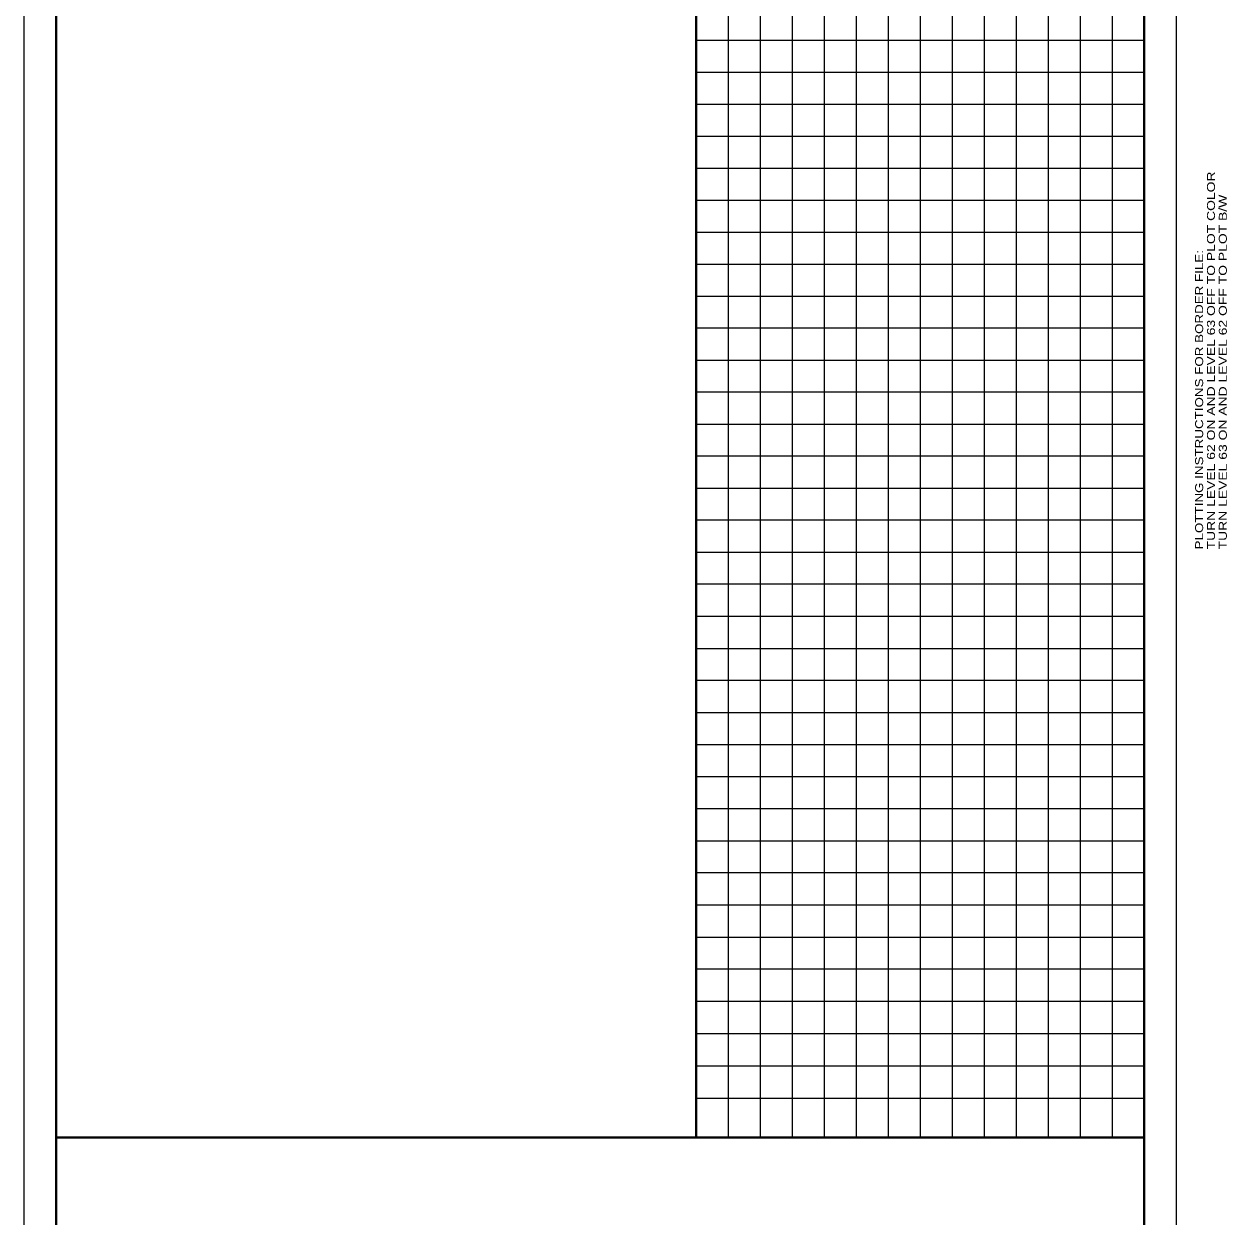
# Model space of a CAD drawing. Extents: x 2363323 to 2367082, y 6956018 to 6980837.
# Drawn here: x 2363323 to 2367082, y 6965978 to 6969706 of the extents above; entities that cross this region are included whole.
import ezdxf

# ---------------------------------------------------------------- set-up
doc = ezdxf.new("R2010")
doc.units = 0
doc.header["$LTSCALE"] = 4.1
doc.layers.add('1', color=7, linetype='Continuous')
for name, color, linetype, lineweight in [('61', 7, 'Continuous', 40), ('62', 7, 'Continuous', 13), ('63', 7, 'Continuous', 13)]:
    doc.layers.add(name, color=color, linetype=linetype, lineweight=lineweight)

msp = doc.modelspace()

# ---------------------------------------------------------------- linework, layer by layer
at = {"layer": '61'}
for p, q in [((2363423.186, 6980156.078), (2363423.186, 6957300.912)), ((2366823.34, 6966225.912), (2363423.186, 6966225.912))]:
    msp.add_line(p, q, dxfattribs=at)
at = {"layer": '61', "lineweight": 13}
msp.add_lwpolyline([(2366923.344, 6957200.912), (2363323.182, 6957200.912), (2363323.182, 6980256.082)], dxfattribs=at)
at = {"layer": '62'}
for p, q in [((2366923.344, 6980256.082), (2366923.344, 6957200.912)), ((2366223.313, 6979505.057), (2366223.313, 6966225.912)), ((2366323.317, 6979505.057), (2366323.317, 6966225.912)), ((2366423.322, 6979505.057), (2366423.322, 6966225.912)), ((2366523.326, 6979505.057), (2366523.326, 6966225.912)), ((2366623.331, 6979505.057), (2366623.331, 6966225.912)), ((2366723.335, 6979505.057), (2366723.335, 6966225.912)), ((2365523.281, 6979456.046), (2365523.281, 6966225.912)), ((2365623.286, 6979456.046), (2365623.286, 6966225.912)), ((2365723.29, 6979456.046), (2365723.29, 6966225.912)), ((2365823.295, 6979456.046), (2365823.295, 6966225.912)), ((2365923.299, 6979456.046), (2365923.299, 6966225.912)), ((2366023.304, 6979456.046), (2366023.304, 6966225.912)), ((2366123.308, 6979456.046), (2366123.308, 6966225.912)), ((2365423.277, 6969655.603), (2366823.34, 6969655.603)), ((2365423.277, 6969555.599), (2366823.34, 6969555.599)), ((2365423.277, 6969455.594), (2366823.34, 6969455.594)), ((2365423.277, 6969355.59), (2366823.34, 6969355.59)), ((2365423.277, 6969255.585), (2366823.34, 6969255.585)), ((2365423.277, 6969155.58), (2366823.34, 6969155.58)), ((2365423.277, 6969055.576), (2366823.34, 6969055.576)), ((2365423.277, 6968955.571), (2366823.34, 6968955.571)), ((2365423.277, 6968855.567), (2366823.34, 6968855.567)), ((2365423.277, 6968756.438), (2366823.34, 6968756.438)), ((2365423.277, 6968655.558), (2366823.34, 6968655.558)), ((2365423.277, 6968556.429), (2366823.34, 6968556.429)), ((2365423.277, 6968455.549), (2366823.34, 6968455.549)), ((2365423.277, 6968356.42), (2366823.34, 6968356.42)), ((2365423.277, 6968255.54), (2366823.34, 6968255.54)), ((2365423.277, 6968156.411), (2366823.34, 6968156.411)), ((2365423.277, 6968055.531), (2366823.34, 6968055.531)), ((2365423.277, 6967956.402), (2366823.34, 6967956.402)), ((2365423.277, 6967855.522), (2366823.34, 6967855.522)), ((2365423.277, 6967754.642), (2366823.34, 6967754.642)), ((2365423.277, 6967655.513), (2366823.34, 6967655.513)), ((2365423.277, 6967554.633), (2366823.34, 6967554.633)), ((2365423.277, 6967453.753), (2366823.34, 6967453.753)), ((2365423.277, 6967354.624), (2366823.34, 6967354.624)), ((2365423.277, 6967253.744), (2366823.34, 6967253.744)), ((2365423.277, 6967152.864), (2366823.34, 6967152.864)), ((2365423.277, 6967053.735), (2366823.34, 6967053.735)), ((2365423.277, 6966952.855), (2366823.34, 6966952.855)), ((2365423.277, 6966851.975), (2366823.34, 6966851.975)), ((2365423.277, 6966752.846), (2366823.34, 6966752.846)), ((2365423.277, 6966651.966), (2366823.34, 6966651.966)), ((2365423.277, 6966551.086), (2366823.34, 6966551.086)), ((2365423.277, 6966450.206), (2366823.34, 6966450.206)), ((2365423.277, 6966349.326), (2366823.34, 6966349.326))]:
    msp.add_line(p, q, dxfattribs=at)
at = {"layer": '62', "lineweight": 40}
for p, q in [((2366823.34, 6980156.078), (2366823.34, 6957300.912)), ((2365423.277, 6979456.046), (2365423.277, 6966225.912))]:
    msp.add_line(p, q, dxfattribs=at)
at = {"layer": '63'}
for p, q in [((2366923.344, 6980256.082), (2366923.344, 6957200.912)), ((2366223.313, 6979505.057), (2366223.313, 6966225.912)), ((2366323.317, 6979505.057), (2366323.317, 6966225.912)), ((2366423.322, 6979505.057), (2366423.322, 6966225.912)), ((2366523.326, 6979505.057), (2366523.326, 6966225.912)), ((2366623.331, 6979505.057), (2366623.331, 6966225.912)), ((2366723.335, 6979505.057), (2366723.335, 6966225.912)), ((2365523.281, 6979456.046), (2365523.281, 6966225.912)), ((2365623.286, 6979456.046), (2365623.286, 6966225.912)), ((2365723.29, 6979456.046), (2365723.29, 6966225.912)), ((2365823.295, 6979456.046), (2365823.295, 6966225.912)), ((2365923.299, 6979456.046), (2365923.299, 6966225.912)), ((2366023.304, 6979456.046), (2366023.304, 6966225.912)), ((2366123.308, 6979456.046), (2366123.308, 6966225.912)), ((2365423.277, 6969655.603), (2366823.34, 6969655.603)), ((2365423.277, 6969555.599), (2366823.34, 6969555.599)), ((2365423.277, 6969455.594), (2366823.34, 6969455.594)), ((2365423.277, 6969355.59), (2366823.34, 6969355.59)), ((2365423.277, 6969255.585), (2366823.34, 6969255.585)), ((2365423.277, 6969155.58), (2366823.34, 6969155.58)), ((2365423.277, 6969055.576), (2366823.34, 6969055.576)), ((2365423.277, 6968955.571), (2366823.34, 6968955.571)), ((2365423.277, 6968855.567), (2366823.34, 6968855.567)), ((2365423.277, 6968756.438), (2366823.34, 6968756.438)), ((2365423.277, 6968655.558), (2366823.34, 6968655.558)), ((2365423.277, 6968556.429), (2366823.34, 6968556.429)), ((2365423.277, 6968455.549), (2366823.34, 6968455.549)), ((2365423.277, 6968356.42), (2366823.34, 6968356.42)), ((2365423.277, 6968255.54), (2366823.34, 6968255.54)), ((2365423.277, 6968156.411), (2366823.34, 6968156.411)), ((2365423.277, 6968055.531), (2366823.34, 6968055.531)), ((2365423.277, 6967956.402), (2366823.34, 6967956.402)), ((2365423.277, 6967855.522), (2366823.34, 6967855.522)), ((2365423.277, 6967754.642), (2366823.34, 6967754.642)), ((2365423.277, 6967655.513), (2366823.34, 6967655.513)), ((2365423.277, 6967554.633), (2366823.34, 6967554.633)), ((2365423.277, 6967453.753), (2366823.34, 6967453.753)), ((2365423.277, 6967354.624), (2366823.34, 6967354.624)), ((2365423.277, 6967253.744), (2366823.34, 6967253.744)), ((2365423.277, 6967152.864), (2366823.34, 6967152.864)), ((2365423.277, 6967053.735), (2366823.34, 6967053.735)), ((2365423.277, 6966952.855), (2366823.34, 6966952.855)), ((2365423.277, 6966851.975), (2366823.34, 6966851.975)), ((2365423.277, 6966752.846), (2366823.34, 6966752.846)), ((2365423.277, 6966651.966), (2366823.34, 6966651.966)), ((2365423.277, 6966551.086), (2366823.34, 6966551.086)), ((2365423.277, 6966450.206), (2366823.34, 6966450.206)), ((2365423.277, 6966349.326), (2366823.34, 6966349.326))]:
    msp.add_line(p, q, dxfattribs=at)
at = {"layer": '63', "lineweight": 40}
for p, q in [((2366823.34, 6980156.078), (2366823.34, 6957300.912)), ((2365423.277, 6979456.046), (2365423.277, 6966225.912))]:
    msp.add_line(p, q, dxfattribs=at)

# ---------------------------------------------------------------- texts
at = {"layer": '1'}
for s, width, p in [('TURN LEVEL 62 ON AND LEVEL 63 OFF TO PLOT COLOR', 1.3, (2367044.537, 6968063.88)), ('TURN LEVEL 63 ON AND LEVEL 62 OFF TO PLOT B/W', 1.3, (2367081.538, 6968063.878)), ('PLOTTING INSTRUCTIONS FOR BORDER FILE:', 1.25, (2367007.535, 6968063.88))]:
    msp.add_text(s, height=25, rotation=90, dxfattribs=dict(at, width=width)).set_placement(p)

doc.saveas('drawing.dxf')
